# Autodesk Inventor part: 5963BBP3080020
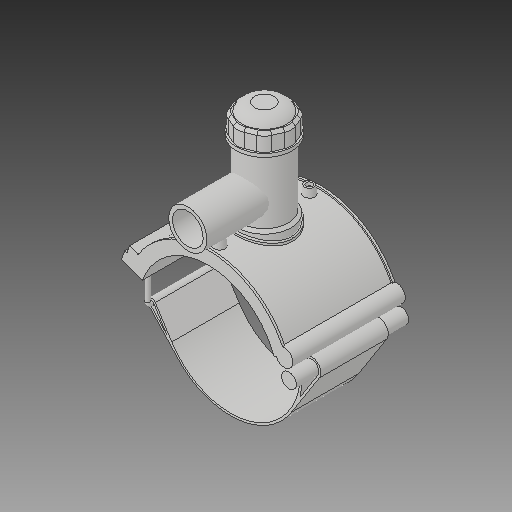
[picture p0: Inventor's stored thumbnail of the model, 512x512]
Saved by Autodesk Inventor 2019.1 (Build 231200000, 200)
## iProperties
Created: 2017-07
Part Number: 5963BBP3080020
Material: Generic
Description: PLASSON TAPPING SADDLE 8''IPS x 2''IPS
Document SubType Name: Modeling
Designer: KIM
Density: 1 g/cm^3
Appearance: Default
Author: KIM
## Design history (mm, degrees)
derived "5963BBP_5963BUP.ipt"
feature "Solid1::5963BBP_5963BUP.ipt"
feature "Solid2::5963BBP_5963BUP.ipt"
feature "Solid3::5963BBP_5963BUP.ipt"
tag "TaggingFeature1"
body "Solid1"
body "Solid2"
body "Solid3"
other parameters: "d0" = 218.7, "d2" = 269.748, "d3" = 54.675, "d4" = 176.022, "d5" = 0, "d6" = 0.1, "d8" = 0, "d19" = 6, "d20" = 6, "d21" = 105.6132, "d23" = 0, "d24" = 52.8066, "d26" = 0, "d27" = 3, "d28" = 3, "d29" = 3, "d30" = 72.9, "d31" = 6, "d32" = 0, "d33" = 0, "d34" = 0.6, "d40" = 131.91984, "d41" = 87.48, "d43" = 0, "d45" = 0, "d47" = 232.4592, "d70" = 15, "d72" = 0, "d73" = 6, "d75" = 5, "d76" = 0, "d77" = 10.935, "d78" = 139.35, "d79" = 15, "d80" = 70.4088, "d82" = 5 deg, "d84" = 4, "d85" = 14, "d86" = 0, "d87" = 3, "d88" = 0, "d89" = 1, "d90" = 1, "d91" = 140.8176, "d92" = 0, "d93" = 0.5, "d94" = 115.10526, "d96" = 258.76584, "d97" = 3.52044, "d98" = 0, "d102" = 2.187, "d120" = 140 deg, "d121" = 24.228, "d122" = 20 deg, "d123" = 507.384, "d124" = 152.2152, "d126" = 0, "d143" = 225.261, "d145" = 26.91692, "d149" = 3.2805, "d150" = 29.60862, "d153" = 176.022, "d154" = 0, "d156" = 126.846, "d157" = 160 deg, "d159" = 6.9984, "d161" = 3.2805, "d162" = 105.6132, "d163" = 0, "d164" = 109.35, "d167" = 21.87, "d168" = 123.7522, "d170" = 3.2805, "d172" = 0, "d173" = 1, "d175" = 109.35, "d176" = 20 deg, "d177" = 15.309, "d178" = 34.992, "d180" = 0, "d183" = 13.9968, "d184" = 12.2472, "d185" = 57.20715, "d186" = 57.20715, "d187" = 126.846, "d188" = 10.4976, "d189" = 15.309, "d190" = 0, "d191" = 190.269, "d193" = 6.9984, "d194" = 6.16077, "d195" = 90 deg, "d197" = 0, "d199" = 0, "d200" = 17.496, "d202" = 0, "d203" = 177.038, "d204" = 83.106, "d205" = 61.236, "d206" = 74.358, "d207" = 132.7785, "d208" = 138.08964, "d209" = 164.64534, "d210" = 75.2328, "d211" = 87.48, "d212" = 69.984, "d213" = 31.4766, "d216" = 0, "d217" = 21.87, "d218" = 21.87, "d219" = 4.374, "d222" = 218.7, "d224" = 0, "d225" = 65.024, "d226" = 60.1, "d227" = 48.08, "d228" = 119.888, "d230" = 4.374, "d_" = 218.7, "B_" = 179.832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
